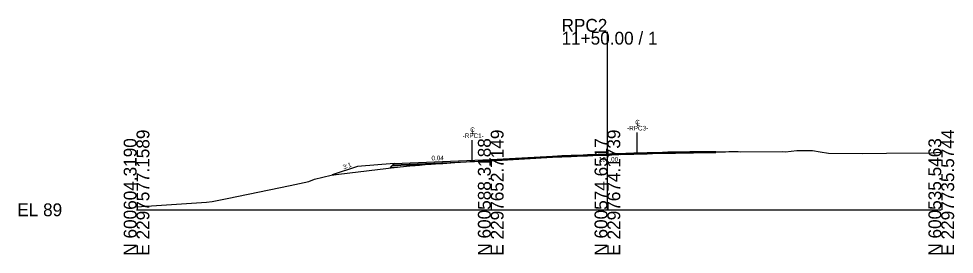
# Model space of a CAD drawing. Extents: x 2124 to 2376, y -10 to 1517.
# Drawn here: x 2124.3 to 2328.3, y 490.3 to 541.6 of the extents above; entities that cross this region are included whole.
import ezdxf

# ---------------------------------------------------------------- set-up
doc = ezdxf.new("R2010")
doc.units = 0
for name, color, linetype in [('Exist Cross Section Cell', 7, 'Continuous'), ('Exist XS Center Line Elevation Label', 7, 'Continuous'), ('Exist XS Ground Line', 7, 'Continuous'), ('Prop CMT Pvmt Course 3 Wedge', 7, 'Continuous'), ('Prop CMT Pvmt Surface', 7, 'Continuous'), ('Prop CMT Pvmt Surface Overlay', 7, 'Continuous'), ('Prop CMT Shld Paved Course 1', 7, 'Continuous'), ('Prop CMT Shld Paved Course 2', 7, 'Continuous'), ('Prop CMT Slope Grass', 7, 'Continuous'), ('Prop XS Earthwork Shape', 7, 'Continuous'), ('Prop XS Label Text', 7, 'Continuous'), ('Prop XS SE Text', 7, 'Continuous'), ('Prop XS Side Slope Text', 7, 'Continuous')]:
    doc.layers.add(name, color=color, linetype=linetype)

msp = doc.modelspace()

# ---------------------------------------------------------------- linework, layer by layer
at = {"layer": 'Exist Cross Section Cell'}
for p, q in [((2252.67, 500), (2252.67, 538.8)), ((2150, 500), (2227.23, 500)), ((2227.23, 500), (2252.67, 500)), ((2252.67, 500), (2325.47, 500))]:
    msp.add_line(p, q, dxfattribs=at)
at = {"layer": 'Exist XS Ground Line'}
msp.add_lwpolyline([(2150, 500.63), (2165.28, 501.66), (2166.47, 501.84), (2169.75, 502.47), (2183.48, 505.28), (2187.57, 506.14), (2188.81, 506.67), (2192.41, 507.58), (2194.14, 507.77), (2206.79, 509.27), (2210.35, 509.64), (2210.77, 509.68), (2211.17, 509.7), (2211.68, 509.74), (2212.92, 509.84), (2214.23, 509.94), (2216.17, 510.07), (2216.79, 510.11), (2219.41, 510.29), (2221.9, 510.46), (2222.65, 510.51), (2224.46, 510.63), (2225.89, 510.73), (2227.23, 510.82), (2228.76, 510.92), (2229.94, 510.99), (2232.13, 511.12), (2232.9, 511.16), (2233.41, 511.18), (2234.91, 511.25), (2235.87, 511.3), (2238.06, 511.46), (2238.65, 511.5), (2239.38, 511.54), (2239.77, 511.56), (2240.34, 511.56), (2241.8, 511.64), (2242.72, 511.68), (2244.76, 511.76), (2247.37, 511.88), (2247.72, 511.89), (2248.34, 511.92), (2250.69, 512.01), (2252.6, 511.99), (2253.65, 512.12), (2256.68, 512.22), (2258.45, 512.28), (2259.58, 512.31), (2260.26, 512.32), (2261.33, 512.35), (2262.54, 512.39), (2264.67, 512.45), (2265.85, 512.49), (2266.22, 512.49), (2266.75, 512.49), (2267.51, 512.49), (2268.47, 512.51), (2270.64, 512.56), (2271.44, 512.57), (2272.94, 512.59), (2274.4, 512.6), (2275.29, 512.61), (2276.56, 512.62), (2277.36, 512.63), (2278.41, 512.65), (2279.15, 512.67), (2280.68, 512.67), (2281.17, 512.67), (2281.77, 512.65), (2290.95, 512.67), (2291.5, 512.66), (2293.98, 512.93), (2296.57, 512.9), (2297.41, 512.89), (2299.07, 512.62), (2300.9, 512.33), (2308.31, 512.27), (2313.51, 512.33), (2323.27, 512.42), (2325.47, 512.55)], dxfattribs=at)
at = {"layer": 'Prop CMT Pvmt Course 3 Wedge'}
msp.add_line((2205.64, 509.57), (2205.28, 509.22), dxfattribs=at)
at = {"layer": 'Prop CMT Pvmt Surface'}
for p, q in [((2276.3, 512.49), (2276.3, 512.74)), ((2205.89, 509.82), (2227.23, 510.68)), ((2206.15, 510.08), (2227.23, 510.93)), ((2227.23, 510.93), (2240.67, 511.7)), ((2227.23, 510.68), (2240.67, 511.45)), ((2213.45, 509.88), (2205.63, 509.56))]:
    msp.add_line(p, q, dxfattribs=at)
for points in [[(2240.67, 511.7), (2241.8, 511.76), (2242.72, 511.8), (2244.76, 511.88), (2247.37, 512), (2247.72, 512.01), (2248.34, 512.04), (2250.69, 512.14), (2252.6, 512.12), (2253.65, 512.24), (2256.68, 512.34), (2258.45, 512.41), (2259.58, 512.43), (2260.26, 512.45), (2261.33, 512.48), (2262.54, 512.52), (2264.67, 512.58), (2265.85, 512.62), (2266.22, 512.61), (2266.75, 512.62), (2267.51, 512.62), (2268.47, 512.64), (2270.64, 512.69), (2271.44, 512.7), (2272.94, 512.71), (2274.4, 512.73), (2275.29, 512.74), (2276.3, 512.74)], [(2240.67, 511.45), (2241.8, 511.51), (2242.72, 511.55), (2244.76, 511.63), (2247.37, 511.75), (2247.72, 511.76), (2248.34, 511.79), (2250.69, 511.89), (2252.6, 511.87), (2253.65, 511.99), (2256.68, 512.09), (2258.45, 512.16), (2259.58, 512.18), (2260.26, 512.2), (2261.33, 512.23), (2262.54, 512.27), (2264.67, 512.33), (2265.85, 512.37), (2266.22, 512.36), (2266.75, 512.37), (2267.51, 512.37), (2268.47, 512.39), (2270.64, 512.44), (2271.44, 512.45), (2272.94, 512.46), (2274.4, 512.48), (2275.29, 512.49), (2276.3, 512.49)]]:
    msp.add_lwpolyline(points, dxfattribs=at)
at = {"layer": 'Prop CMT Pvmt Surface Overlay'}
for p, q in [((2276.3, 512.49), (2276.3, 512.74)), ((2205.89, 509.82), (2227.23, 510.68)), ((2206.15, 510.08), (2227.23, 510.93)), ((2227.23, 510.93), (2240.67, 511.7)), ((2227.23, 510.68), (2240.67, 511.45))]:
    msp.add_line(p, q, dxfattribs=at)
for points in [[(2240.67, 511.7), (2241.8, 511.76), (2242.72, 511.8), (2244.76, 511.88), (2247.37, 512), (2247.72, 512.01), (2248.34, 512.04), (2250.69, 512.14), (2252.6, 512.12), (2253.65, 512.24), (2256.68, 512.34), (2258.45, 512.41), (2259.58, 512.43), (2260.26, 512.45), (2261.33, 512.48), (2262.54, 512.52), (2264.67, 512.58), (2265.85, 512.62), (2266.22, 512.61), (2266.75, 512.62), (2267.51, 512.62), (2268.47, 512.64), (2270.64, 512.69), (2271.44, 512.7), (2272.94, 512.71), (2274.4, 512.73), (2275.29, 512.74), (2276.3, 512.74)], [(2240.67, 511.45), (2241.8, 511.51), (2242.72, 511.55), (2244.76, 511.63), (2247.37, 511.75), (2247.72, 511.76), (2248.34, 511.79), (2250.69, 511.89), (2252.6, 511.87), (2253.65, 511.99), (2256.68, 512.09), (2258.45, 512.16), (2259.58, 512.18), (2260.26, 512.2), (2261.33, 512.23), (2262.54, 512.27), (2264.67, 512.33), (2265.85, 512.37), (2266.22, 512.36), (2266.75, 512.37), (2267.51, 512.37), (2268.47, 512.39), (2270.64, 512.44), (2271.44, 512.45), (2272.94, 512.46), (2274.4, 512.48), (2275.29, 512.49), (2276.3, 512.49)]]:
    msp.add_lwpolyline(points, dxfattribs=at)
at = {"layer": 'Prop CMT Shld Paved Course 1'}
msp.add_lwpolyline([(2206.15, 510.08), (2205.89, 509.82)], dxfattribs=at)
at = {"layer": 'Prop CMT Shld Paved Course 2'}
for p, q in [((2206.88, 509.28), (2205.28, 509.22)), ((2213.45, 509.88), (2205.63, 509.56))]:
    msp.add_line(p, q, dxfattribs=at)
msp.add_lwpolyline([(2205.89, 509.83), (2205.63, 509.56)], dxfattribs=at)
at = {"layer": 'Prop CMT Slope Grass'}
for p, q in [((2206.15, 510.08), (2198.15, 509.44)), ((2206.15, 510.08), (2205.28, 509.22)), ((2198.15, 509.44), (2192.63, 507.61)), ((2205.28, 509.22), (2206.88, 509.28))]:
    msp.add_line(p, q, dxfattribs=at)
at = {"layer": 'Prop XS Earthwork Shape'}
msp.add_lwpolyline([(2206.79, 509.27), (2206.88, 509.28), (2205.28, 509.22), (2206.15, 510.08), (2198.15, 509.44), (2192.63, 507.61), (2194.14, 507.77)], close=True, dxfattribs=at)
at = {"layer": 'Prop XS Label Text'}
for p, q in [((2259.17, 512.42), (2259.17, 516.87)), ((2223.21, 510.77), (2223.21, 515.21))]:
    msp.add_line(p, q, dxfattribs=at)

# ---------------------------------------------------------------- texts
at = {"layer": 'Exist Cross Section Cell'}
for s, p in [('RPC2', (2242.67, 538.8)), ('11+50.00 / 1', (2242.67, 536)), ('EL 89', (2124, 498.6))]:
    msp.add_text(s, height=2.8, dxfattribs=at).set_placement(p)
for s, p in [('E 2297577.1589', (2152.8, 490)), ('E 2297652.7149', (2230.03, 490)), ('E 2297674.1739', (2255.47, 490)), ('E 2297735.5744', (2328.27, 490)), ('N 600604.3190', (2150, 490)), ('N 600588.3188', (2227.23, 490)), ('N 600574.6517', (2252.67, 490)), ('N 600535.5463', (2325.47, 490))]:
    msp.add_text(s, height=2.8, rotation=90, dxfattribs=at).set_placement(p)
at = {"layer": 'Exist XS Center Line Elevation Label'}
msp.add_text('101.00', height=1, dxfattribs=at).set_placement((2250.8, 510.5))
at = {"layer": 'Prop XS Label Text'}
for s, p in [('-RPC3-', (2256.96, 517.29)), ('C', (2258.73, 518.6)), ('L', (2259, 518.28)), ('-RPC1-', (2221.11, 515.64)), ('C', (2222.76, 516.95)), ('L', (2223.04, 516.62))]:
    msp.add_text(s, height=1, dxfattribs=at).set_placement(p)
at = {"layer": 'Prop XS SE Text'}
msp.add_text('0.04', height=1, rotation=0.8783, dxfattribs=at).set_placement((2214.32, 510.77))
at = {"layer": 'Prop XS Side Slope Text'}
msp.add_text('3:1', height=1, rotation=20.6597, dxfattribs=at).set_placement((2195.19, 508.76))

doc.saveas('drawing.dxf')
